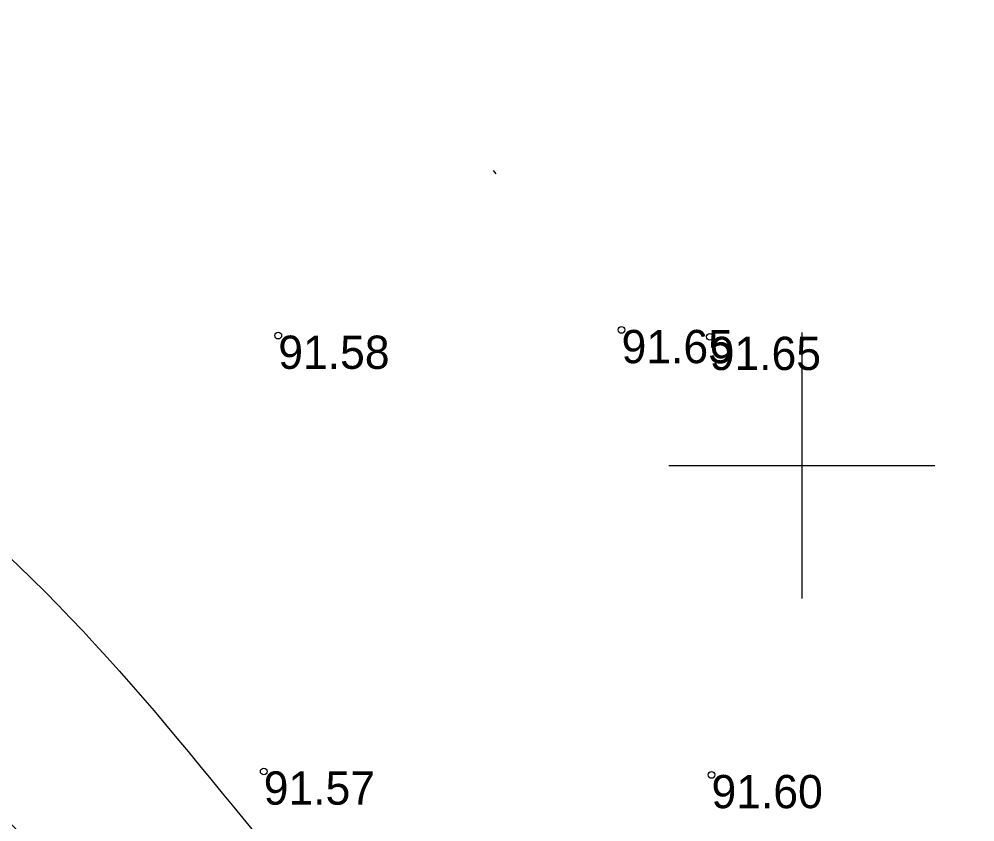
# Model space of a CAD drawing. Extents: x 316000 to 728450, y 314368 to 726000.
# Drawn here: x 725911.7 to 726019.5, y 315459.8 to 315550.4 of the extents above; entities that cross this region are included whole.
import ezdxf

# ---------------------------------------------------------------- set-up
doc = ezdxf.new("R2010")
doc.units = 0
for name, color, linetype in [('GEOD_ELEM_####_####_#', 7, 'Continuous'), ('RELJ_AATZ_####_TKST_#', 7, 'Continuous'), ('RELJ_ELEM_####_####_#', 7, 'Continuous'), ('RELJ_HORZ_PAMT_####_#', 7, 'Continuous'), ('RELJ_NOGA_####_####_#', 7, 'Continuous')]:
    doc.layers.add(name, color=color, linetype=linetype)

msp = doc.modelspace()

# ---------------------------------------------------------------- linework, layer by layer
at = {"layer": 'GEOD_ELEM_####_####_#'}
for p, q in [((726000, 315515), (726000, 315500)), ((725985, 315500), (726000, 315500)), ((726000, 315500), (726000, 315485)), ((726000, 315500), (726015, 315500))]:
    msp.add_line(p, q, dxfattribs=at)
at = {"layer": 'RELJ_ELEM_####_####_#'}
for centre in [(725979.67, 315515.3), (725940.96, 315514.66), (725989.61, 315514.53), (725939.32, 315465.51), (725989.81, 315465.11)]:
    msp.add_circle(centre, 0.375, dxfattribs=at)
at = {"layer": 'RELJ_HORZ_PAMT_####_#'}
msp.add_line((725965.19, 315533.28), (725965.49, 315532.89), dxfattribs=at)
msp.add_spline([(726116.34, 315699.09), (726105.94, 315702.69), (726040.13, 315715), (725990.82, 315710.42), (725942.03, 315708.25), (725920.28, 315706.77), (725880.37, 315714.51), (725859.05, 315708.68), (725859.05, 315672.66), (725851.26, 315613.97), (725853.47, 315568.9), (725841, 315555.79), (725885.56, 315509.63), (725935.94, 315461.49), (725983.42, 315406.25), (726032.86, 315360.51), (726082.85, 315311.19), (726122.23, 315248.76), (726137.05, 315229.29), (726180.19, 315183.1), (726194.52, 315168.27), (726211.91, 315146.93), (726212.51, 315143.16)], degree=3, dxfattribs=at)
at = {"layer": 'RELJ_NOGA_####_####_#'}
for points in [[(726259.12, 315084.51), (726262.72, 315089.26), (726261.56, 315090.84), (726260.2, 315092.42), (726257.29, 315095.53), (726218.91, 315136.38), (726180.31, 315176.84), (726128.67, 315229.97), (726063.7, 315298.11), (725999.9, 315366.09), (725937.21, 315432.09), (725876.35, 315495.23), (725810.58, 315563.08), (725744.7, 315632.91)], [(725740.86, 315626.98), (725805.54, 315558.12), (725870.39, 315491.15), (725932.8, 315426.8), (725994.98, 315360.84), (726059.66, 315292.12), (726075.75, 315275.46), (726092.08, 315259.04), (726108.47, 315242.67), (726124.69, 315226.14), (726193.27, 315154.03), (726250.06, 315092.6), (726256.32, 315085.83), (726258.82, 315084.29), (726259.12, 315084.51)]]:
    msp.add_spline(points, degree=3, dxfattribs=at)

# ---------------------------------------------------------------- texts
at = {"layer": 'RELJ_AATZ_####_TKST_#'}
for s, p in [('91.58', (725940.96, 315510.91)), ('91.65', (725979.67, 315511.55)), ('91.65', (725989.61, 315510.78)), ('91.57', (725939.32, 315461.76)), ('91.60', (725989.81, 315461.36))]:
    msp.add_text(s, height=3.75, dxfattribs=at).set_placement(p)

doc.saveas('drawing.dxf')
